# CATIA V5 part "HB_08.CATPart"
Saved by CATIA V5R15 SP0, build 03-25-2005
Part number: HB_08
Material "Bordeaux Red": density 7860 kg/m3, Young's modulus 2e+11 Pa, Poisson ratio 0.266
Bounding box of the stored display mesh (mm): x -79 to 0, y 0 to 632, z 0 to 113.2
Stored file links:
  E:\#01 CATIA Lecture Materials\#06 DMU\#11 DMU Page01 KIN EX11\HB_08.CATPart
  E:\공학과제\HB-16.CATPart
  C:\Program Files\Dassault Systemes\B20\win_b64\startup\materials\Catalog.CATMaterial
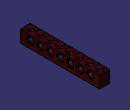
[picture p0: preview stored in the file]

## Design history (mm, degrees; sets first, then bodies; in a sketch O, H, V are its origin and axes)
Body1 (main body), material "Bordeaux Red"
  Sketch1 on xy-plane, origin (0, 0, 0), H (1, 0, 0), V (0, 1, 0)
    circle A1 centre (-39.5, 39.5) radius 24.5
    point P1 (-39.5, 39.5)
    reference projected line E1 (0, 0) -> (0, 1264)
    reference projected line E2 (-79, 0) -> (-79, 1264)
    reference projected line E3 (-79, 0) -> (0, 0)
    radius A1 = 24.5
    distance P1 E3 = 39.5
    equidistance: E1 E2 P1
  Pad1: profile Sketch1, direction (0, 0, 1), length 113.2
  RectPattern1: of the body so far, direction 1 instances 8, spacing 79, along yz-plane
  Sketch2 on zx-plane, origin (0, 0, 0), H (-1, 0, 0), V (0, 0, 1)
    point P1 (0, 96)
    line L1 (0, 96) -> (79, 96)
    line L2 (79, 96) -> (79, 0)
    line L3 (79, 0) -> (0, 0)
    line L4 (0, 0) -> (0, 96)
    point P3 (79, 0)
    distance L2 L4 = 79
    length L2 = 96
    coincidence: P1 V, P3 H
    horizontal: L1 H, L3 H
    vertical: L2 V, L4 V
  Pad2: profile Sketch2, direction (0, 1, 0), length 632 {= 632mm}
  Plane1: type Offset, RefPlane zx-plane, Offset 79
  Sketch3 on Plane1, origin (0, 79, 0), H (-1, 0, 0), V (0, 0, 1)
    axis line L1 (95.3003, 56) -> (-23.8651, 56)
    reference projected line E1 (79, 96) -> (0, 96) from edge [start face of Pad2 | face of Pad2 from Sketch2.L1]
    point P3 (79, 56)
    line L2 (79, 56) -> (79, 85.25)
    line L3 (79, 85.25) -> (69, 85.25)
    line L4 (69, 85.25) -> (69, 80.25)
    line L5 (69, 80.25) -> (10, 80.25)
    line L6 (10, 80.25) -> (10, 85.25)
    point P8 (10, 85.25)
    line L7 (10, 85.25) -> (0, 85.25)
    point P9 (0, 85.25)
    line L8 (0, 85.25) -> (0, 56)
    point P10 (0, 56)
    reference projected line E2 (79, 0) -> (79, 96) from edge [start face of Pad2 | face of Pad2 from Sketch2.L2]
    distance L1 E1 = 40
    distance L8 L6 = 10
    distance L4 L2 = 10
    distance L5 L1 = 24.25
    distance L7 L1 = 29.25
    horizontal: L1 H, L3 H, L5 H, L7 H
    coincidence: P3 L1, P8 L3, P9 V, P10 L1, L2 E2
    vertical: L2 V, L4 V, L6 V, L8 V
  Groove1: profile Sketch3, axis Sketch3.L1, angle 360
  RectPattern2: of Groove1, direction 1 instances 7 {= RectPattern1.Nb1 - 1}, spacing 79, along edge [face of Pad2 from Sketch2.L4 | face of Pad2 from Sketch2.L1]
  Shell1: ExtOffset 0, Face face of Pad2, IntOffset 10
